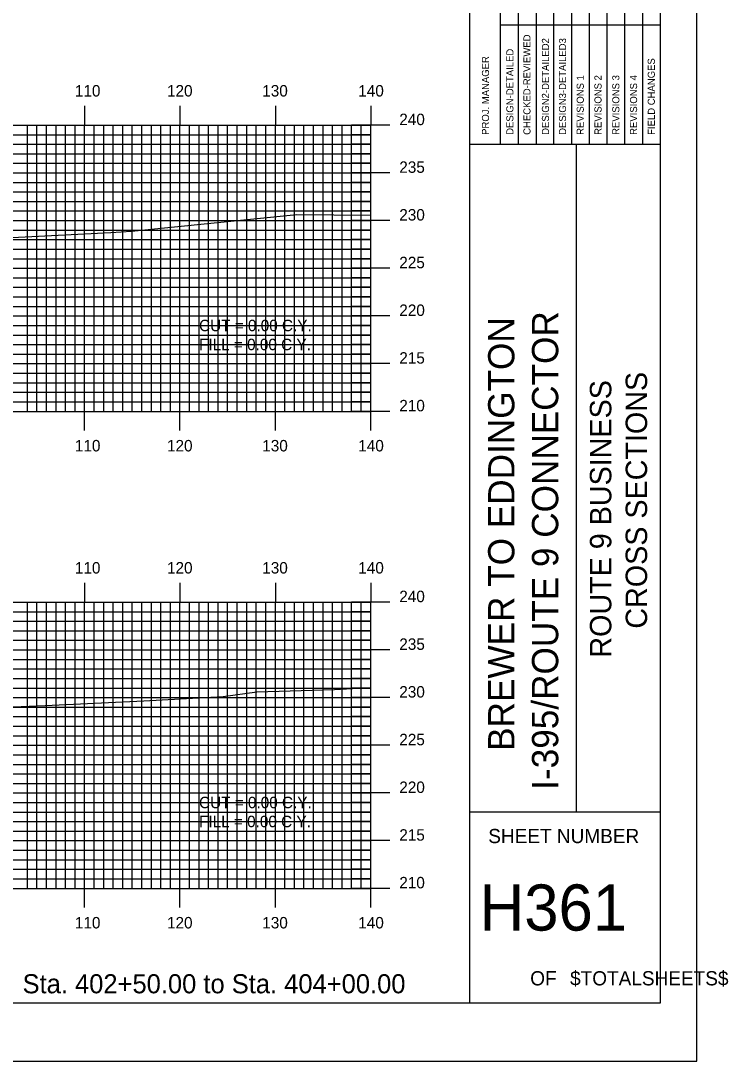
# Model space of a CAD drawing. Extents: x 850955 to 851298, y 364785 to 365005.
# Drawn here: x 851224 to 851298.2, y 364785.1 to 364894.2 of the extents above; entities that cross this region are included whole.
import ezdxf

# ---------------------------------------------------------------- set-up
doc = ezdxf.new("R2010")
doc.units = 0
for name, color, linetype in [('BORDER', 7, 'Continuous'), ('D_Text_Standard', 7, 'Continuous'), ('H_V ANNOTATION', 7, 'Continuous'), ('MAJOR', 7, 'Continuous'), ('MINOR', 7, 'Continuous'), ('PLOT BOUNDARY', 7, 'Continuous'), ('S_Roadway_Centerline', 7, 'Continuous')]:
    doc.layers.add(name, color=color, linetype=linetype)

msp = doc.modelspace()

# ---------------------------------------------------------------- linework, layer by layer
at = {"layer": 'BORDER'}
for p, q in [((851271.08, 364791.23), (851271.08, 365001.23)), ((851271.08, 364881.24), (851291.08, 364881.24)), ((851282.26, 364811.24), (851282.26, 364881.24)), ((851271.08, 364811.24), (851291.08, 364811.24))]:
    msp.add_line(p, q, dxfattribs=at)
msp.add_lwpolyline([(850971.08, 364791.23), (851291.08, 364791.23), (851291.08, 365001.23), (850971.08, 365001.23)], close=True, dxfattribs=at)
for points in [[(851276.17, 364881.24), (851276.17, 364916.24)], [(851278.04, 364916.24), (851278.04, 364881.24)], [(851279.9, 364881.24), (851279.9, 364916.24)], [(851281.76, 364881.24), (851281.76, 364916.24)], [(851283.63, 364881.24), (851283.63, 364916.24)], [(851285.49, 364881.24), (851285.49, 364916.24)], [(851287.35, 364881.24), (851287.35, 364916.24)], [(851289.22, 364881.24), (851289.22, 364916.24)], [(851274.31, 364881.24), (851274.31, 364914.83)], [(851274.31, 364893.74), (851291.08, 364893.74)]]:
    msp.add_lwpolyline(points, dxfattribs=at)
at = {"layer": 'MAJOR'}
for p, q in [((851230.68, 364885.24), (851230.68, 364883.23)), ((851240.68, 364885.24), (851240.68, 364883.23)), ((851250.68, 364885.24), (851250.68, 364883.23)), ((851260.68, 364885.24), (851260.68, 364883.23)), ((850980.68, 364883.23), (851260.68, 364883.23)), ((850980.68, 364883.23), (851260.68, 364883.23)), ((851230.68, 364853.23), (851230.68, 364883.23)), ((851240.68, 364853.23), (851240.68, 364883.23)), ((851250.68, 364853.23), (851250.68, 364883.23)), ((851262.68, 364883.23), (851258.67, 364883.23)), ((851260.68, 364853.23), (851260.68, 364883.23)), ((851260.68, 364853.23), (851260.68, 364883.23)), ((850980.68, 364878.23), (851260.68, 364878.23)), ((851262.68, 364878.23), (851258.67, 364878.23)), ((850980.68, 364873.23), (851260.68, 364873.23)), ((851262.68, 364873.23), (851258.67, 364873.23)), ((850980.68, 364868.23), (851260.68, 364868.23)), ((851262.68, 364868.23), (851258.67, 364868.23)), ((850980.68, 364863.23), (851260.68, 364863.23)), ((851262.68, 364863.23), (851258.67, 364863.23)), ((850980.68, 364858.23), (851260.68, 364858.23)), ((851262.68, 364858.23), (851258.67, 364858.23)), ((850980.68, 364853.23), (851260.68, 364853.23)), ((850980.68, 364853.23), (851260.68, 364853.23)), ((851230.68, 364851.23), (851230.68, 364853.23)), ((851240.68, 364851.23), (851240.68, 364853.23)), ((851250.68, 364851.23), (851250.68, 364853.23)), ((851262.68, 364853.23), (851258.67, 364853.23)), ((851260.68, 364851.23), (851260.68, 364853.23)), ((851230.68, 364835.24), (851230.68, 364833.23)), ((851240.68, 364835.24), (851240.68, 364833.23)), ((851250.68, 364835.24), (851250.68, 364833.23)), ((851260.68, 364835.24), (851260.68, 364833.23)), ((850980.68, 364833.23), (851260.68, 364833.23)), ((850980.68, 364833.23), (851260.68, 364833.23)), ((851230.68, 364803.23), (851230.68, 364833.23)), ((851240.68, 364803.23), (851240.68, 364833.23)), ((851250.68, 364803.23), (851250.68, 364833.23)), ((851262.68, 364833.23), (851258.67, 364833.23)), ((851260.68, 364803.23), (851260.68, 364833.23)), ((851260.68, 364803.23), (851260.68, 364833.23)), ((850980.68, 364828.23), (851260.68, 364828.23)), ((851262.68, 364828.23), (851258.67, 364828.23)), ((850980.68, 364823.23), (851260.68, 364823.23)), ((851262.68, 364823.23), (851258.67, 364823.23)), ((850980.68, 364818.23), (851260.68, 364818.23)), ((851262.68, 364818.23), (851258.67, 364818.23)), ((850980.68, 364813.23), (851260.68, 364813.23)), ((851262.68, 364813.23), (851258.67, 364813.23)), ((850980.68, 364808.23), (851260.68, 364808.23)), ((851262.68, 364808.23), (851258.67, 364808.23)), ((850980.68, 364803.23), (851260.68, 364803.23)), ((850980.68, 364803.23), (851260.68, 364803.23)), ((851230.68, 364801.23), (851230.68, 364803.23)), ((851240.68, 364801.23), (851240.68, 364803.23)), ((851250.68, 364801.23), (851250.68, 364803.23)), ((851262.68, 364803.23), (851258.67, 364803.23)), ((851260.68, 364801.23), (851260.68, 364803.23))]:
    msp.add_line(p, q, dxfattribs=at)
at = {"layer": 'MINOR'}
for p, q in [((851224.68, 364853.23), (851224.68, 364883.23)), ((851225.68, 364853.23), (851225.68, 364883.23)), ((851226.68, 364853.23), (851226.68, 364883.23)), ((851227.68, 364853.23), (851227.68, 364883.23)), ((851228.68, 364853.23), (851228.68, 364883.23)), ((851229.68, 364853.23), (851229.68, 364883.23)), ((851231.68, 364853.23), (851231.68, 364883.23)), ((851232.68, 364853.23), (851232.68, 364883.23)), ((851233.68, 364853.23), (851233.68, 364883.23)), ((851234.68, 364853.23), (851234.68, 364883.23)), ((851235.68, 364853.23), (851235.68, 364883.23)), ((851236.68, 364853.23), (851236.68, 364883.23)), ((851237.68, 364853.23), (851237.68, 364883.23)), ((851238.68, 364853.23), (851238.68, 364883.23)), ((851239.68, 364853.23), (851239.68, 364883.23)), ((851241.68, 364853.23), (851241.68, 364883.23)), ((851242.68, 364853.23), (851242.68, 364883.23)), ((851243.68, 364853.23), (851243.68, 364883.23)), ((851244.68, 364853.23), (851244.68, 364883.23)), ((851245.68, 364853.23), (851245.68, 364883.23)), ((851246.68, 364853.23), (851246.68, 364883.23)), ((851247.68, 364853.23), (851247.68, 364883.23)), ((851248.68, 364853.23), (851248.68, 364883.23)), ((851249.68, 364853.23), (851249.68, 364883.23)), ((851251.68, 364853.23), (851251.68, 364883.23)), ((851252.68, 364853.23), (851252.68, 364883.23)), ((851253.68, 364853.23), (851253.68, 364883.23)), ((851254.68, 364853.23), (851254.68, 364883.23)), ((851255.68, 364853.23), (851255.68, 364883.23)), ((851256.68, 364853.23), (851256.68, 364883.23)), ((851257.68, 364853.23), (851257.68, 364883.23)), ((851258.68, 364853.23), (851258.68, 364883.23)), ((851259.68, 364853.23), (851259.68, 364883.23)), ((850980.68, 364882.23), (851260.68, 364882.23)), ((851260.68, 364882.23), (851258.67, 364882.23)), ((850980.68, 364881.23), (851260.68, 364881.23)), ((851260.68, 364881.23), (851258.67, 364881.23)), ((850980.68, 364880.23), (851260.68, 364880.23)), ((851260.68, 364880.23), (851258.67, 364880.23)), ((850980.68, 364879.23), (851260.68, 364879.23)), ((851260.68, 364879.23), (851258.67, 364879.23)), ((850980.68, 364877.23), (851260.68, 364877.23)), ((851260.68, 364877.23), (851258.67, 364877.23)), ((850980.68, 364876.23), (851260.68, 364876.23)), ((851260.68, 364876.23), (851258.67, 364876.23)), ((850980.68, 364875.23), (851260.68, 364875.23)), ((851260.68, 364875.23), (851258.67, 364875.23)), ((850980.68, 364874.23), (851260.68, 364874.23)), ((851260.68, 364874.23), (851258.67, 364874.23)), ((850980.68, 364872.23), (851260.68, 364872.23)), ((851260.68, 364872.23), (851258.67, 364872.23)), ((850980.68, 364871.23), (851260.68, 364871.23)), ((851260.68, 364871.23), (851258.67, 364871.23)), ((850980.68, 364870.23), (851260.68, 364870.23)), ((851260.68, 364870.23), (851258.67, 364870.23)), ((850980.68, 364869.23), (851260.68, 364869.23)), ((851260.68, 364869.23), (851258.67, 364869.23)), ((850980.68, 364867.23), (851260.68, 364867.23)), ((851260.68, 364867.23), (851258.67, 364867.23)), ((850980.68, 364866.23), (851260.68, 364866.23)), ((851260.68, 364866.23), (851258.67, 364866.23)), ((850980.68, 364865.23), (851260.68, 364865.23)), ((851260.68, 364865.23), (851258.67, 364865.23)), ((850980.68, 364864.23), (851260.68, 364864.23)), ((851260.68, 364864.23), (851258.67, 364864.23)), ((850980.68, 364862.23), (851260.68, 364862.23)), ((850980.68, 364861.23), (851260.68, 364861.23)), ((851260.68, 364862.23), (851258.67, 364862.23)), ((851260.68, 364861.23), (851258.67, 364861.23)), ((850980.68, 364860.23), (851260.68, 364860.23)), ((851260.68, 364860.23), (851258.67, 364860.23)), ((850980.68, 364859.23), (851260.68, 364859.23)), ((851260.68, 364859.23), (851258.67, 364859.23)), ((850980.68, 364857.23), (851260.68, 364857.23)), ((851260.68, 364857.23), (851258.67, 364857.23)), ((850980.68, 364856.23), (851260.68, 364856.23)), ((851260.68, 364856.23), (851258.67, 364856.23)), ((850980.68, 364855.23), (851260.68, 364855.23)), ((851260.68, 364855.23), (851258.67, 364855.23)), ((850980.68, 364854.23), (851260.68, 364854.23)), ((851260.68, 364854.23), (851258.67, 364854.23)), ((851224.68, 364803.23), (851224.68, 364833.23)), ((851225.68, 364803.23), (851225.68, 364833.23)), ((851226.68, 364803.23), (851226.68, 364833.23)), ((851227.68, 364803.23), (851227.68, 364833.23)), ((851228.68, 364803.23), (851228.68, 364833.23)), ((851229.68, 364803.23), (851229.68, 364833.23)), ((851231.68, 364803.23), (851231.68, 364833.23)), ((851232.68, 364803.23), (851232.68, 364833.23)), ((851233.68, 364803.23), (851233.68, 364833.23)), ((851234.68, 364803.23), (851234.68, 364833.23)), ((851235.68, 364803.23), (851235.68, 364833.23)), ((851236.68, 364803.23), (851236.68, 364833.23)), ((851237.68, 364803.23), (851237.68, 364833.23)), ((851238.68, 364803.23), (851238.68, 364833.23)), ((851239.68, 364803.23), (851239.68, 364833.23)), ((851241.68, 364803.23), (851241.68, 364833.23)), ((851242.68, 364803.23), (851242.68, 364833.23)), ((851243.68, 364803.23), (851243.68, 364833.23)), ((851244.68, 364803.23), (851244.68, 364833.23)), ((851245.68, 364803.23), (851245.68, 364833.23)), ((851246.68, 364803.23), (851246.68, 364833.23)), ((851247.68, 364803.23), (851247.68, 364833.23)), ((851248.68, 364803.23), (851248.68, 364833.23)), ((851249.68, 364803.23), (851249.68, 364833.23)), ((851251.68, 364803.23), (851251.68, 364833.23)), ((851252.68, 364803.23), (851252.68, 364833.23)), ((851253.68, 364803.23), (851253.68, 364833.23)), ((851254.68, 364803.23), (851254.68, 364833.23)), ((851255.68, 364803.23), (851255.68, 364833.23)), ((851256.68, 364803.23), (851256.68, 364833.23)), ((851257.68, 364803.23), (851257.68, 364833.23)), ((851258.68, 364803.23), (851258.68, 364833.23)), ((851259.68, 364803.23), (851259.68, 364833.23)), ((850980.68, 364832.23), (851260.68, 364832.23)), ((851260.68, 364832.23), (851258.67, 364832.23)), ((850980.68, 364831.23), (851260.68, 364831.23)), ((851260.68, 364831.23), (851258.67, 364831.23)), ((850980.68, 364830.23), (851260.68, 364830.23)), ((851260.68, 364830.23), (851258.67, 364830.23)), ((850980.68, 364829.23), (851260.68, 364829.23)), ((851260.68, 364829.23), (851258.67, 364829.23)), ((850980.68, 364827.23), (851260.68, 364827.23)), ((851260.68, 364827.23), (851258.67, 364827.23)), ((850980.68, 364826.23), (851260.68, 364826.23)), ((850980.68, 364825.23), (851260.68, 364825.23)), ((851260.68, 364826.23), (851258.67, 364826.23)), ((851260.68, 364825.23), (851258.67, 364825.23)), ((850980.68, 364824.23), (851260.68, 364824.23)), ((851260.68, 364824.23), (851258.67, 364824.23)), ((850980.68, 364822.23), (851260.68, 364822.23)), ((851260.68, 364822.23), (851258.67, 364822.23)), ((850980.68, 364821.23), (851260.68, 364821.23)), ((851260.68, 364821.23), (851258.67, 364821.23)), ((850980.68, 364820.23), (851260.68, 364820.23)), ((851260.68, 364820.23), (851258.67, 364820.23)), ((850980.68, 364819.23), (851260.68, 364819.23)), ((851260.68, 364819.23), (851258.67, 364819.23)), ((850980.68, 364817.23), (851260.68, 364817.23)), ((851260.68, 364817.23), (851258.67, 364817.23)), ((850980.68, 364816.23), (851260.68, 364816.23)), ((851260.68, 364816.23), (851258.67, 364816.23)), ((850980.68, 364815.23), (851260.68, 364815.23)), ((851260.68, 364815.23), (851258.67, 364815.23)), ((850980.68, 364814.23), (851260.68, 364814.23)), ((851260.68, 364814.23), (851258.67, 364814.23)), ((850980.68, 364812.23), (851260.68, 364812.23)), ((851260.68, 364812.23), (851258.67, 364812.23)), ((850980.68, 364811.23), (851260.68, 364811.23)), ((851260.68, 364811.23), (851258.67, 364811.23)), ((850980.68, 364810.23), (851260.68, 364810.23)), ((851260.68, 364810.23), (851258.67, 364810.23)), ((850980.68, 364809.23), (851260.68, 364809.23)), ((851260.68, 364809.23), (851258.67, 364809.23)), ((850980.68, 364807.23), (851260.68, 364807.23)), ((851260.68, 364807.23), (851258.67, 364807.23)), ((850980.68, 364806.23), (851260.68, 364806.23)), ((851260.68, 364806.23), (851258.67, 364806.23)), ((850980.68, 364805.23), (851260.68, 364805.23)), ((851260.68, 364805.23), (851258.67, 364805.23)), ((850980.68, 364804.23), (851260.68, 364804.23)), ((851260.68, 364804.23), (851258.67, 364804.23))]:
    msp.add_line(p, q, dxfattribs=at)
at = {"layer": 'PLOT BOUNDARY'}
msp.add_lwpolyline([(850954.89, 364785.11), (851294.89, 364785.11), (851294.89, 365005.11), (850954.89, 365005.11)], close=True, dxfattribs=at)
at = {"layer": 'S_Roadway_Centerline'}
for points in [[(851152.54, 364861.87), (851156.45, 364863.05), (851158.61, 364864.02), (851165.44, 364867.21), (851170.38, 364867.63), (851171.19, 364867.84), (851171.46, 364867.88), (851172.54, 364867.95), (851178.66, 364868.69), (851188.25, 364869.03), (851204.56, 364870.34), (851215.86, 364871.28), (851221.64, 364871.38), (851233.42, 364871.99), (851234.52, 364872.04), (851235.61, 364872.1), (851252.93, 364873.86), (851260.68, 364873.78)], [(851151.37, 364813.08), (851156.48, 364813.57), (851157.32, 364813.95), (851168.69, 364819.56), (851170.22, 364819.9), (851171.62, 364820.26), (851175.19, 364821.01), (851176.2, 364821.08), (851176.44, 364821.08), (851188.48, 364821.65), (851189.58, 364821.7), (851200.72, 364821.58), (851207.97, 364821.64), (851221.43, 364822.19), (851226.53, 364822.38), (851236.9, 364822.87), (851245.22, 364823.33), (851248.75, 364823.82), (851256.88, 364824.07), (851260.68, 364824.28)]]:
    msp.add_lwpolyline(points, dxfattribs=at)

# ---------------------------------------------------------------- texts
at = {"layer": 'BORDER'}
for s, height, p in [('CHECKED-REVIEWED', 0.7455, (851277.44, 364882.21)), ('DESIGN2-DETAILED2', 0.7455, (851279.38, 364882.21)), ('DESIGN3-DETAILED3', 0.7455, (851281.17, 364882.21)), ('DESIGN-DETAILED', 0.7455, (851275.65, 364882.21)), ('PROJ. MANAGER', 0.7455, (851273.09, 364882.21)), ('FIELD CHANGES', 0.7455, (851290.48, 364882.21)), ('REVISIONS 1', 0.7455, (851283.03, 364882.21)), ('REVISIONS 2', 0.7455, (851284.89, 364882.21)), ('REVISIONS 3', 0.7455, (851286.76, 364882.21)), ('REVISIONS 4', 0.7455, (851288.62, 364882.21)), ('I-395/ROUTE 9 CONNECTOR', 2.7557, (851280.35, 364813.56)), ('BREWER TO EDDINGTON', 2.7557, (851275.75, 364817.64)), ('CROSS SECTIONS', 2.25, (851289.67, 364830.45)), ('ROUTE 9 BUSINESS', 2.25, (851285.92, 364827.41))]:
    msp.add_text(s, height=height, rotation=90, dxfattribs=at).set_placement(p)
for s, height, p in [('SHEET NUMBER', 1.4905, (851273.01, 364807.97)), ('H361', 4.839, (851272.11, 364798.8)), ('OF', 1.491, (851277.41, 364793.06)), ('$TOTALSHEETS$', 1.4905, (851281.59, 364793.06))]:
    msp.add_text(s, height=height, dxfattribs=at).set_placement(p)
at = {"layer": 'D_Text_Standard'}
for s, p in [('CUT = 0.00 C.Y.', (851242.68, 364861.63)), ('FILL = 0.00 C.Y.', (851242.68, 364859.64)), ('CUT = 0.00 C.Y.', (851242.68, 364811.63)), ('FILL = 0.00 C.Y.', (851242.68, 364809.64))]:
    msp.add_text(s, height=1.2, dxfattribs=at).set_placement(p)
at = {"layer": 'H_V ANNOTATION'}
for s, height, p in [('110', 1.2, (851229.66, 364886.23)), ('120', 1.2, (851239.32, 364886.23)), ('130', 1.2, (851249.31, 364886.23)), ('140', 1.2, (851259.38, 364886.23)), ('240', 1.2, (851263.68, 364883.23)), ('235', 1.2, (851263.68, 364878.23)), ('230', 1.2, (851263.68, 364873.23)), ('225', 1.2, (851263.68, 364868.23)), ('220', 1.2, (851263.68, 364863.23)), ('215', 1.2, (851263.68, 364858.23)), ('210', 1.2, (851263.68, 364853.23)), ('110', 1.2, (851229.66, 364849.03)), ('120', 1.2, (851239.32, 364849.03)), ('130', 1.2, (851249.31, 364849.03)), ('140', 1.2, (851259.38, 364849.03)), ('110', 1.2, (851229.66, 364836.23)), ('120', 1.2, (851239.32, 364836.23)), ('130', 1.2, (851249.31, 364836.23)), ('140', 1.2, (851259.38, 364836.23)), ('240', 1.2, (851263.68, 364833.23)), ('235', 1.2, (851263.68, 364828.23)), ('230', 1.2, (851263.68, 364823.23)), ('225', 1.2, (851263.68, 364818.23)), ('220', 1.2, (851263.68, 364813.23)), ('215', 1.2, (851263.68, 364808.23)), ('210', 1.2, (851263.68, 364803.23)), ('110', 1.2, (851229.66, 364799.03)), ('120', 1.2, (851239.32, 364799.03)), ('130', 1.2, (851249.31, 364799.03)), ('140', 1.2, (851259.38, 364799.03)), ('Sta. 402+50.00 to Sta. 404+00.00', 2.0004, (851224.17, 364792.23))]:
    msp.add_text(s, height=height, dxfattribs=at).set_placement(p)

doc.saveas('drawing.dxf')
